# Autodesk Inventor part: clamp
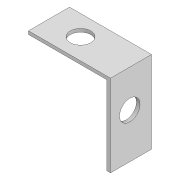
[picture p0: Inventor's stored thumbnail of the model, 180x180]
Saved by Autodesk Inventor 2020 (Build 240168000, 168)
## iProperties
Created: 2019-10
Part Number: clamp
Material: Generic
Document SubType Name: Modeling
Designer: Dell
Density: 1 g/cm^3
Appearance: Default
Author: Dell
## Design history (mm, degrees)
sketch "Sketch1"
  geometry: L1 (-0.043, 3.455)-(19.957, 3.455); L2 (19.957, 3.455)-(19.957, -16.545); L3 (19.957, -16.545)-(19.082, -16.545); L4 (19.082, -16.545)-(19.082, 2.673); L5 (19.082, 2.673)-(-0.043, 2.673); L6 (-0.043, 2.673)-(-0.043, 3.455)
  constraints: 12 end point, 4 perpendicular, 1 horizontal
  dimensions: "d0" = 20 distance of L1.start L1.end; "d1" = 20 distance of L1.end L2.end
extrude "Extrusion1" new body sketch "Sketch1" distance "d2" = 10; taper "d3" = 0 deg
sketch "Sketch2"
  geometry: C1 r 2.5 at (7.618, 5.075)
  constraints: 1 centre point
  dimensions: "d4" = 5 diameter of C1
extrude "Extrusion2" cut sketch "Sketch2" distance "d5" = 1; taper "d6" = 0 deg
sketch "Sketch3"
  geometry: C1 r 2.5 at (4.694, 10.916)
  constraints: 1 centre point
  dimensions: "d7" = 5 diameter of C1
extrude "Extrusion3" cut sketch "Sketch3" distance "d8" = 1; taper "d9" = 0 deg
body "Solid1"
